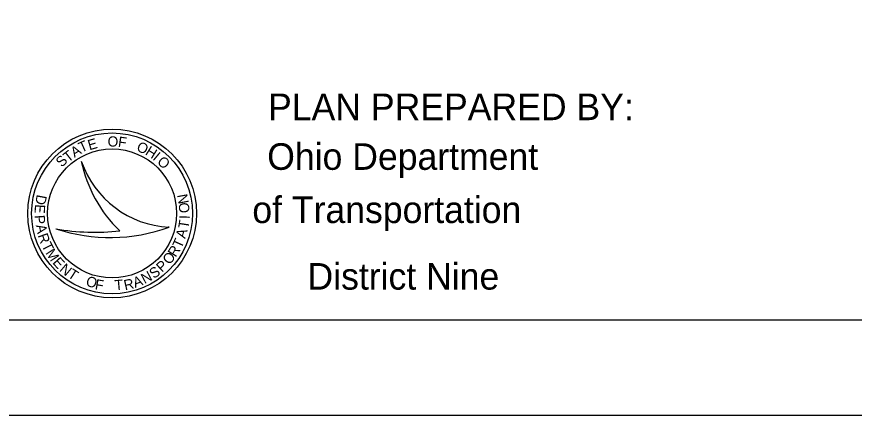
# Model space of a CAD drawing. Extents: x 0 to 34, y 0 to 22.
# Drawn here: x 2.29 to 6.697, y 0 to 2.097 of the extents above; entities that cross this region are included whole.
import ezdxf

# ---------------------------------------------------------------- set-up
doc = ezdxf.new("R2010")
doc.units = 0
for name, color, linetype in [('SH_Border', 7, 'Continuous'), ('SH_Cut_Line', 7, 'Continuous'), ('SH_Data', 7, 'Continuous'), ('SH_Text', 7, 'Continuous')]:
    doc.layers.add(name, color=color, linetype=linetype)

msp = doc.modelspace()

# ---------------------------------------------------------------- linework, layer by layer
at = {"layer": 'SH_Border'}
msp.add_lwpolyline([(1.5, 21.5), (33.5, 21.5), (33.5, 0.5), (1.5, 0.5)], close=True, dxfattribs=at)
at = {"layer": 'SH_Cut_Line'}
msp.add_lwpolyline([(0, 0), (34, 0), (34, 22), (0, 22)], close=True, dxfattribs=at)
at = {"layer": 'SH_Data'}
for p in [(3.0907, 0.9861), (3.0907, 0.9927)]:
    msp.add_line(p, (3.0907, 0.9927), dxfattribs=at)
for radius in [0.4439, 0.4233, 0.3394]:
    msp.add_circle((2.7919, 1.0622), radius, dxfattribs=at)
for centre, radius, start, end in [((3.1169, 1.504), 0.5148, 198.9257, 267.1657), ((3.3217, 1.4796), 0.7064, 191.6379, 226.0963), ((2.7825, 1.8347), 0.8995, 251.4527, 290.0832), ((2.7014, 2.0871), 1.1241, 259.4964, 276.6689)]:
    msp.add_arc(centre, radius, start, end, dxfattribs=at)

# ---------------------------------------------------------------- texts
for s, height, rotation, p in [('E', 0.0541, 16.043, (2.6727, 1.3942)), ('O', 0.0539, 359.9091, (2.7682, 1.414)), ('F', 0.0541, 351.9674, (2.8208, 1.414)), ('A', 0.0541, 31.1261, (2.5937, 1.3547)), ('T', 0.0541, 23.9678, (2.6299, 1.3811)), ('O', 0.0539, 335.793, (2.9162, 1.3942)), ('H', 0.0541, 327.9389, (2.9623, 1.3745)), ('S', 0.0541, 45.4775, (2.5279, 1.3021)), ('T', 0.0541, 37.6476, (2.5608, 1.3284)), ('I', 0.0541, 320.2199, (3.0018, 1.3481)), ('O', 0.0541, 318.5022, (3.0248, 1.3284)), ('D', 0.0539, 259.12, (2.3963, 1.1639)), ('N', 0.0539, 100.5286, (3.196, 1.1178)), ('E', 0.0541, 266.6484, (2.3864, 1.1112)), ('O', 0.0541, 92.9555, (3.1993, 1.0651)), ('P', 0.0541, 274.2753, (2.3831, 1.052)), ('T', 0.0541, 81.2026, (3.1927, 0.9796)), ('I', 0.0541, 88.6028, (3.1993, 1.0322)), ('A', 0.0541, 281.7405, (2.3897, 0.9993)), ('A', 0.0541, 73.5293, (3.1762, 0.9269)), ('R', 0.0539, 289.4003, (2.3996, 0.9467)), ('T', 0.0541, 66.0112, (3.1565, 0.8742)), ('T', 0.0541, 296.9819, (2.4193, 0.894)), ('R', 0.0541, 58.3738, (3.1269, 0.8282)), ('M', 0.0541, 303.081, (2.4391, 0.8545)), ('O', 0.0541, 50.7234, (3.094, 0.7887)), ('E', 0.0541, 312.2703, (2.4753, 0.8018)), ('N', 0.0541, 319.7501, (2.5115, 0.7624)), ('P', 0.0539, 43.1954, (3.0545, 0.7492)), ('T', 0.0541, 327.4174, (2.5542, 0.7294)), ('N', 0.0541, 28.0344, (2.9623, 0.69)), ('S', 0.0541, 35.6162, (3.0117, 0.7163)), ('O', 0.0541, 342.6135, (2.6497, 0.6834)), ('F', 0.0541, 350.1546, (2.699, 0.6636)), ('T', 0.0541, 5.2461, (2.8076, 0.657)), ('R', 0.0541, 12.9016, (2.8603, 0.657)), ('A', 0.0541, 20.3744, (2.913, 0.6702))]:
    msp.add_text(s, height=height, rotation=rotation, dxfattribs=at).set_placement(p)
for s, p in [('Ohio Department ', (3.6081, 1.2916)), ('of Transportation', (3.5297, 1.0116)), ('District Nine', (3.8201, 0.6611))]:
    msp.add_text(s, height=0.14, dxfattribs=at).set_placement(p)
at = {"layer": 'SH_Text'}
msp.add_text('PLAN PREPARED BY:', height=0.14, dxfattribs=at).set_placement((3.6125, 1.553))

doc.saveas('drawing.dxf')
